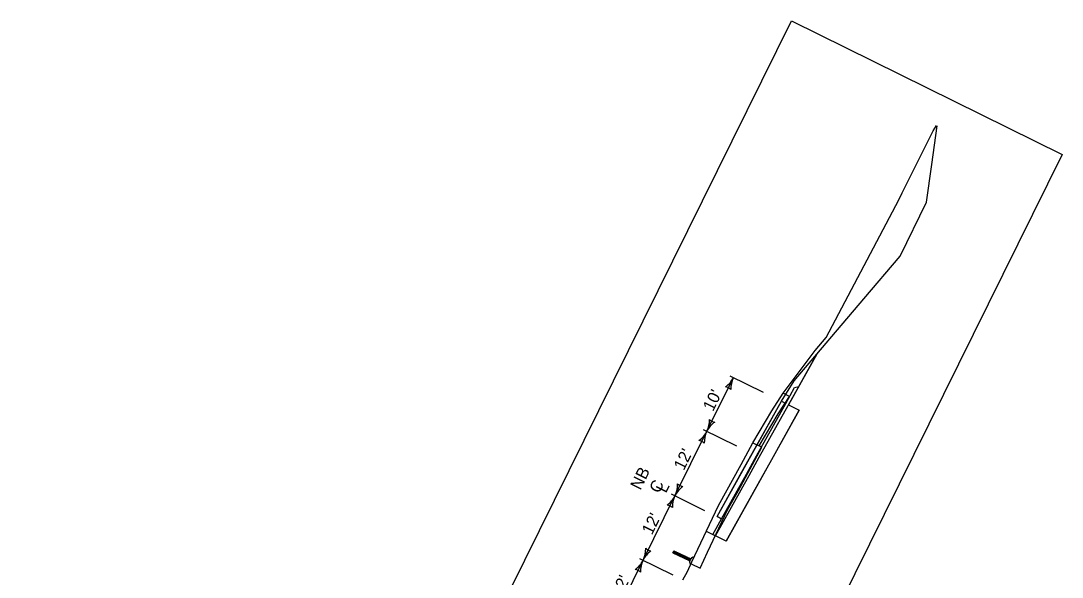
# Model space of a CAD drawing. Extents: x 14104283 to 14128447, y 8633203 to 8671666.
# Drawn here: x 14117091 to 14117786, y 8667442 to 8667813 of the extents above; entities that cross this region are included whole.
import ezdxf

# ---------------------------------------------------------------- set-up
doc = ezdxf.new("R2010")
doc.units = 0
for name, color, linetype in [('Cell', 7, 'Continuous'), ('Default', 7, 'Continuous'), ('dsnCellElements', 7, 'Continuous'), ('dsnShadingPaved', 7, 'Continuous'), ('dsnTextFinalPlan', 7, 'Continuous'), ('TC_Subbase', 7, 'Continuous'), ('TC_SubgradeTreatment', 7, 'Continuous'), ('TC_SubstrataExistingPavement', 7, 'Continuous'), ('Terrain', 7, 'Continuous')]:
    doc.layers.add(name, color=color, linetype=linetype)

# ---------------------------------------------------------------- blocks, each defined once
blk = doc.blocks.new('LT')
at = {"layer": 'dsnCellElements'}
for centre, radius, start, end in [((-3.56, 0), 1.64, 342.2666, 17.7333), ((0, 4.25), 4.25, 241.9275, 270), ((0, -4.25), 4.25, 90, 118.0725)]:
    blk.add_arc(centre, radius, start, end, dxfattribs=at)

msp = doc.modelspace()

# ---------------------------------------------------------------- linework, layer by layer
at = {"layer": 'Cell'}
for p, q in [((14117526.29, 8667458.15), (14117526.92, 8667459.5)), ((14117526.29, 8667458.15), (14117537.62, 8667452.81)), ((14117526.96, 8667457.84), (14117526.61, 8667458.83)), ((14117526.92, 8667459.5), (14117538.25, 8667454.16)), ((14117527.68, 8667457.5), (14117526.97, 8667459.47)), ((14117528.4, 8667457.16), (14117527.69, 8667459.13)), ((14117529.12, 8667456.82), (14117528.41, 8667458.8)), ((14117529.84, 8667456.48), (14117529.13, 8667458.46)), ((14117530.55, 8667456.14), (14117529.84, 8667458.12)), ((14117531.27, 8667455.8), (14117530.56, 8667457.78)), ((14117531.99, 8667455.47), (14117531.28, 8667457.44)), ((14117532.71, 8667455.13), (14117532, 8667457.1)), ((14117533.43, 8667454.79), (14117532.72, 8667456.76)), ((14117534.15, 8667454.45), (14117533.44, 8667456.43)), ((14117534.86, 8667454.11), (14117534.15, 8667456.09)), ((14117535.58, 8667453.77), (14117534.87, 8667455.75)), ((14117536.3, 8667453.43), (14117535.59, 8667455.41)), ((14117537.02, 8667453.1), (14117536.31, 8667455.07)), ((14117537.67, 8667452.93), (14117537.03, 8667454.73)), ((14117537.3, 8667452.14), (14117538.57, 8667454.83)), ((14117538.57, 8667454.83), (14117538.25, 8667454.16)), ((14117538.32, 8667450.84), (14117540.22, 8667454.87)), ((14117538.32, 8667450.84), (14117540.22, 8667454.87)), ((14117539.55, 8667455.19), (14117538.57, 8667454.83)), ((14117538.57, 8667454.83), (14117539.55, 8667455.19)), ((14117540.22, 8667454.87), (14117539.55, 8667455.19)), ((14117539.55, 8667455.19), (14117540.22, 8667454.87)), ((14117537.62, 8667452.81), (14117537.3, 8667452.14)), ((14117537.3, 8667452.14), (14117537.65, 8667451.16)), ((14117537.3, 8667452.14), (14117537.65, 8667451.16)), ((14117538.25, 8667454.16), (14117537.62, 8667452.81)), ((14117537.65, 8667451.16), (14117538.32, 8667450.84)), ((14117537.65, 8667451.16), (14117538.32, 8667450.84)), ((14117538.01, 8667453.65), (14117537.75, 8667454.4))]:
    msp.add_line(p, q, dxfattribs=at)
at = {"layer": 'Default'}
for p, q in [((14117598.68, 8667559.44), (14117601.66, 8667557.97)), ((14117555.7, 8667482.41), (14117558.69, 8667480.93))]:
    msp.add_line(p, q, dxfattribs=at)
for points in [[(14117555.7, 8667482.41), (14117572.34, 8667512.24), (14117579.14, 8667524.42), (14117598.68, 8667559.44)], [(14117558.69, 8667480.93), (14117575.33, 8667510.77), (14117582.13, 8667522.95), (14117601.66, 8667557.97)]]:
    msp.add_lwpolyline(points, dxfattribs=at)
at = {"layer": 'dsnShadingPaved'}
msp.add_lwpolyline([(14117555.7, 8667482.41), (14117598.68, 8667559.44), (14117607.21, 8667573.1), (14117622.34, 8667590.93), (14117603.46, 8667557.08), (14117610.61, 8667553.5), (14117561.78, 8667465.97), (14117552.83, 8667470.43), (14117558.69, 8667480.93)], close=True, dxfattribs=at)
at = {"layer": 'dsnTextFinalPlan'}
for p, q in [((14117548.9, 8667539.32), (14117566.63, 8667575.17)), ((14117564.18, 8667576.38), (14117586.41, 8667565.39)), ((14117527.63, 8667496.29), (14117548.9, 8667539.32)), ((14117546.45, 8667540.53), (14117568.68, 8667529.54)), ((14117506.35, 8667453.26), (14117527.63, 8667496.29)), ((14117525.18, 8667497.5), (14117547.41, 8667486.51)), ((14117485.08, 8667410.23), (14117506.35, 8667453.26)), ((14117503.9, 8667454.47), (14117526.13, 8667443.48))]:
    msp.add_line(p, q, dxfattribs=at)
msp.add_lwpolyline([(14117090.92, 8666772.68), (14117605.48, 8667813.41), (14117786.12, 8667724.1), (14117271.55, 8666683.37)], close=True, dxfattribs=at)
at = {"layer": 'TC_Subbase'}
for p, q in [((14117610.24, 8667569.24), (14117622.34, 8667590.93)), ((14117601.66, 8667557.97), (14117607.52, 8667568.47)), ((14117607.52, 8667568.47), (14117610.24, 8667569.24)), ((14117552.83, 8667470.43), (14117558.69, 8667480.93)), ((14117548.56, 8667472.55), (14117554.63, 8667469.55))]:
    msp.add_line(p, q, dxfattribs=at)
msp.add_lwpolyline([(14117554.63, 8667469.55), (14117577.13, 8667509.88), (14117583.92, 8667522.06), (14117610.24, 8667569.24)], dxfattribs=at)
at = {"layer": 'TC_SubgradeTreatment'}
for p, q in [((14117603.46, 8667557.08), (14117610.61, 8667553.5)), ((14117561.78, 8667465.97), (14117554.63, 8667469.55))]:
    msp.add_line(p, q, dxfattribs=at)
msp.add_lwpolyline([(14117561.78, 8667465.97), (14117584.28, 8667506.3), (14117591.07, 8667518.48), (14117610.61, 8667553.5)], dxfattribs=at)
at = {"layer": 'TC_SubstrataExistingPavement'}
for points in [[(14117579.66, 8667531.63), (14117583.85, 8667529.56), (14117596.54, 8667551), (14117604.08, 8667562.62), (14117599.9, 8667564.69)], [(14117538.36, 8667450.82), (14117544.34, 8667447.86), (14117549.44, 8667458.73), (14117562.63, 8667486.83), (14117570.07, 8667499.82), (14117585.64, 8667528.68), (14117583.85, 8667529.56)]]:
    msp.add_lwpolyline(points, dxfattribs=at)
at = {"layer": 'Terrain'}
for points in [[(14117598.68, 8667559.44), (14117607.21, 8667573.1), (14117653.67, 8667627.85), (14117677.86, 8667656.36), (14117695.64, 8667692.3), (14117699.13, 8667717.39), (14117702.74, 8667743.39)], [(14117677.14, 8667693.9), (14117679.3, 8667698.54), (14117699.97, 8667739.99), (14117702.29, 8667743.61)], [(14117532.86, 8667440.08), (14117535.95, 8667445.67), (14117538.96, 8667452.1), (14117556.65, 8667489.78), (14117571.88, 8667517.2), (14117579.66, 8667531.63), (14117592.36, 8667553.06), (14117599.9, 8667564.69), (14117621.16, 8667593.21), (14117628.6, 8667602.05), (14117677.14, 8667693.9)]]:
    msp.add_lwpolyline(points, dxfattribs=at)

# ---------------------------------------------------------------- block references
at = {"layer": 'dsnTextFinalPlan'}
for p, xscale, yscale, rotation in [((14117566.63, 8667575.17), 3.942400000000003, 3.9424000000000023, 63.69110745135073), ((14117548.9, 8667539.32), 3.942400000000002, 3.9424000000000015, -116.30889254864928), ((14117548.9, 8667539.32), 3.942400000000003, 3.9424000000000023, 63.69110745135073), ((14117527.63, 8667496.29), 3.942400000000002, 3.9424000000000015, -116.30889254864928), ((14117527.63, 8667496.29), 3.942400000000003, 3.9424000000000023, 63.69110745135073), ((14117506.35, 8667453.26), 3.942400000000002, 3.9424000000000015, -116.30889254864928), ((14117506.35, 8667453.26), 3.942400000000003, 3.9424000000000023, 63.69110745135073)]:
    msp.add_blockref('LT', p, dxfattribs=dict(at, xscale=xscale, yscale=yscale, rotation=rotation))

# ---------------------------------------------------------------- texts
for s, p in [("10'", (14117553.01, 8667552.1)), ("12'", (14117533.51, 8667512.65)), ('NB', (14117504.56, 8667499.61)), ('C', (14117517.19, 8667497.41)), ('L', (14117521.63, 8667497.65)), ("12'", (14117512.23, 8667469.63)), ("12'", (14117491.71, 8667428.12))]:
    msp.add_text(s, height=8, rotation=63.69111, dxfattribs=at).set_placement(p)

doc.saveas('drawing.dxf')
